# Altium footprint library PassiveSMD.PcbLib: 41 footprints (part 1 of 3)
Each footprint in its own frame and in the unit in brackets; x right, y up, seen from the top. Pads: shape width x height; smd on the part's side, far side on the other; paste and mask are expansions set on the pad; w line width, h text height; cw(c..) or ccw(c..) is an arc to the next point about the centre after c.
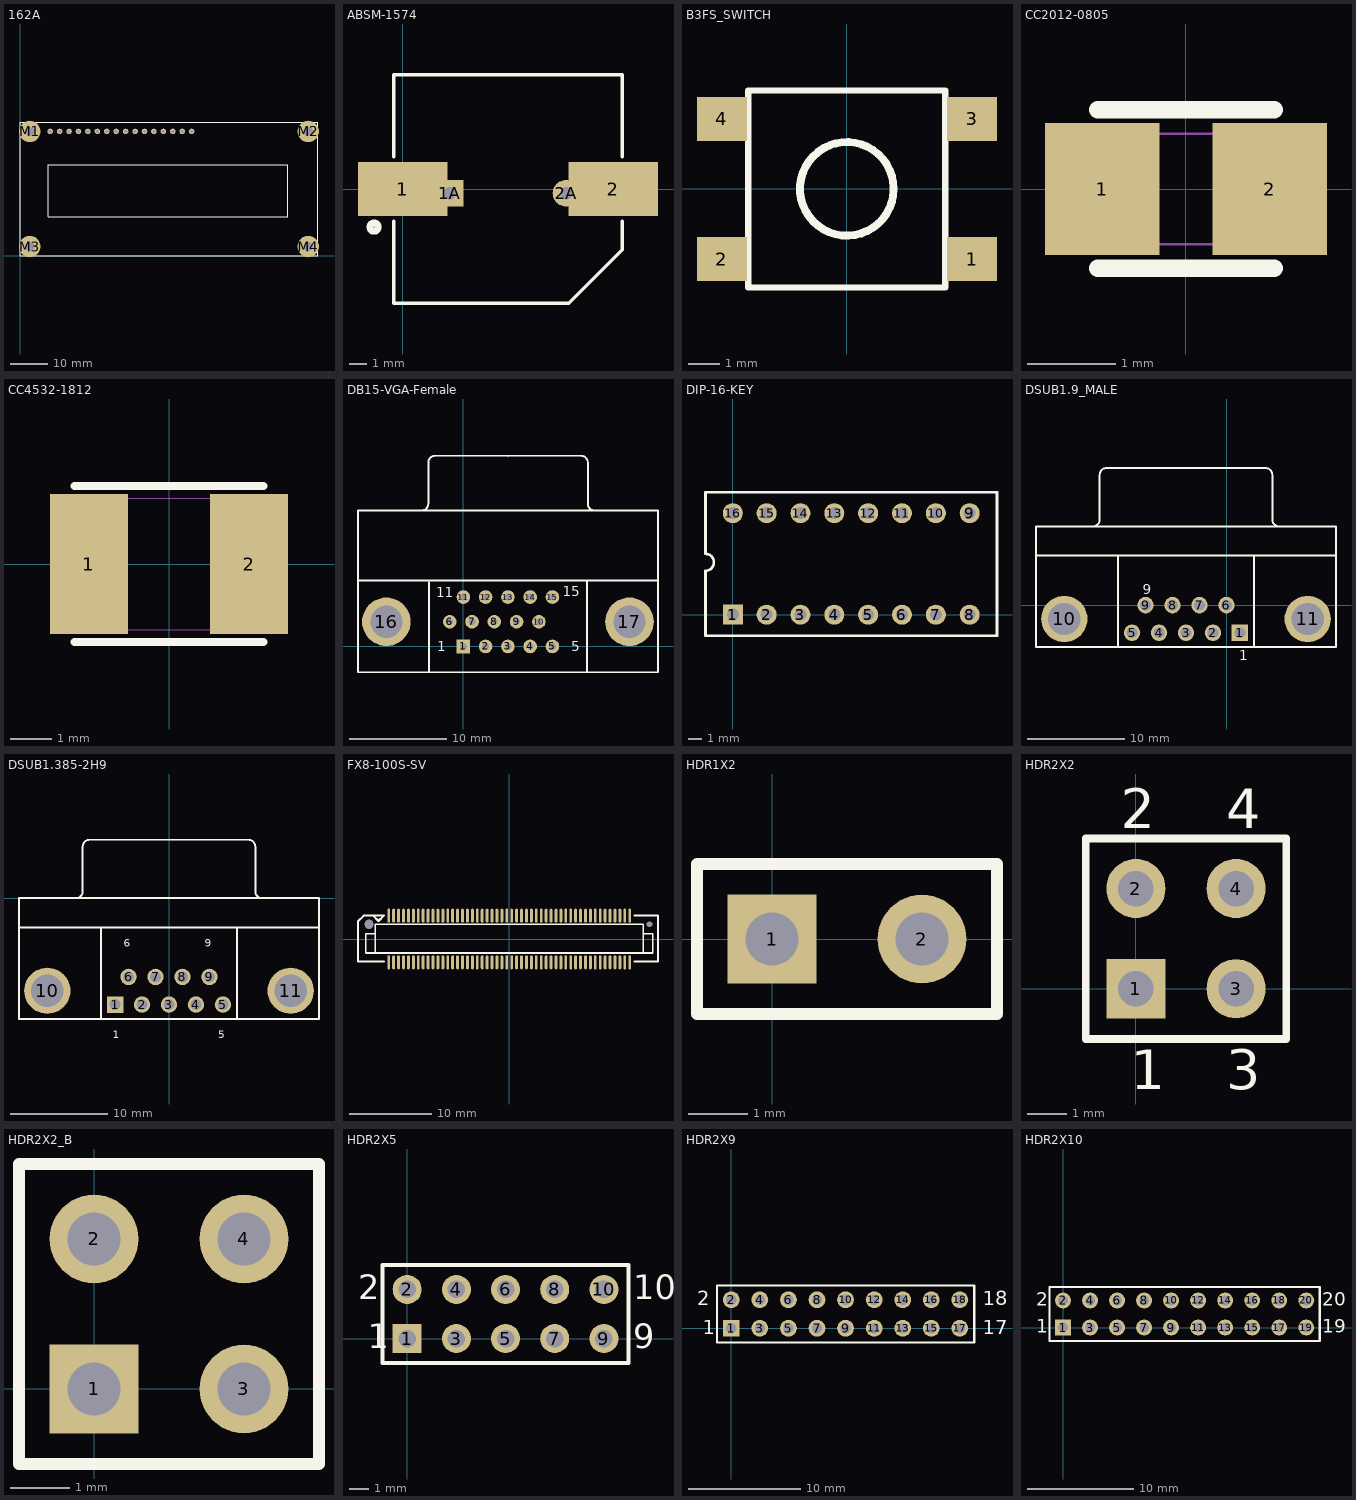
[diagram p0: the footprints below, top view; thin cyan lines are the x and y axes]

## 162A [mm]
pads (20):
  round 1.5 hole 0.9: 1(8.001,33.503) 2(10.541,33.503) 3(13.081,33.503) 4(15.621,33.503) 5(18.161,33.503) 6(20.701,33.503) 7(23.241,33.503) 8(25.781,33.503) 9(28.321,33.503) 10(30.861,33.503) 11(33.401,33.503) 12(35.941,33.503) 13(38.481,33.503) 14(41.021,33.503) 15(43.561,33.503) 16(46.101,33.503)
  round 5.8 / inner round 0 / far side round 0 hole 2.5 unplated: M1(2.501,33.503) M2(77.501,33.503) M3(2.501,2.503) M4(77.501,2.503)
Top Overlay:
  lines w0.2: 0.001,0.003 80.001,0.003 80.001,36.003 0.001,36.003 0.001,0.003 ; 7.501,10.503 72.001,10.503 72.001,24.503 7.501,24.503 7.501,10.503

## ABSM-1574 [mm]
pads (4):
  rect 5x3 smd: 1(0,0) 2(11.8,0)
  rect 1.5x1.5 hole 0.7: 1A(2.65,-0.24)
  round 1.5 hole 0.7: 2A(9.15,-0.24)
Top Overlay:
  circle w0.4: c-1.6,-2.134 r0.227
  lines w0.2: -0.5,-1.8 -0.5,-6.4 9.3,-6.4 12.3,-3.4 12.3,-1.8 ; -0.5,1.8 -0.5,6.4 12.3,6.4 12.3,1.8

## B3FS_SWITCH [mm]
pads (4):
  rect 1.6x1.4 smd: 1(4.01,-2.25) 2(-4,-2.25) 3(4.01,2.24) 4(-4,2.24)
Top Overlay:
  circle w0.254: c0,0 r1.5
  lines w0.2: -3.16,-3.16 3.15,-3.16 3.15,3.15 -3.16,3.15 -3.16,-3.16

## CC2012-0805 [mm]
pads (2):
  rect 1.3x1.5 smd: 1(-0.95,0) 2(0.95,0)
Top Overlay:
  lines w0.2: -1,-0.9 1,-0.9 ; -1,0.9 1,0.9
Mechanical 15:
  lines w0.025: -0.975,-0.625 0.975,-0.625 0.975,0.625 -0.975,0.625 -0.975,-0.625

## CC4532-1812 [mm]
pads (2):
  rect 1.9x3.4 smd: 1(-1.95,0) 2(1.95,0)
Top Overlay:
  lines w0.2: -2.3,-1.9 2.3,-1.9 ; -2.3,1.9 2.3,1.9
Mechanical 15:
  lines w0.025: -2.25,-1.6 -2.25,1.6 2.25,1.6 2.25,-1.6 -2.25,-1.6

## DB15-VGA-Female [mm]
pads (17):
  rect 1.4x1.4 hole 0.7: 1(0,0)
  round 1.4 hole 0.7: 2(2.29,0) 3(4.58,0) 4(6.87,0) 5(9.16,0) 6(-1.4,2.54) 7(0.89,2.54) 8(3.18,2.54) 9(5.47,2.54) 10(7.76,2.54) 11(0,5.08) 12(2.29,5.08) 13(4.58,5.08) 14(6.87,5.08) 15(9.16,5.08)
  round 5 hole 3.3: 16(-7.915,2.54) 17(17.075,2.54)
Top Overlay:
  lines w0.2: -10.83,6.77 20.01,6.77 ; -4.3,13.975 ccw(c-4.3,14.67) -3.605,14.67 -3.605,18.91 cw(c-2.91,18.91) -2.91,19.605 4.595,19.59 12.1,19.605 cw(c12.1,18.91) 12.795,18.91 12.795,14.67 ccw(c13.49,14.67) 13.49,13.975 ; -3.535,-2.65 -3.535,6.57 ; 12.725,-2.65 12.725,6.65 ; -10.83,-2.65 20.01,-2.65 20.01,13.97 -10.83,13.97 -10.83,-2.65
  text "1" at -2.7,-0.5 h1
  text "15" at 10.195,5.17 h1
  text "5" at 11.1,-0.5 h1
  text "11" at -2.805,5.07 h1

## DIP-16-KEY [mm]
pads (16):
  rect 1.5x1.5 hole 0.9: 1(0,0)
  round 1.5 hole 0.9: 2(2.54,0) 3(5.08,0) 4(7.62,0) 5(10.16,0) 6(12.7,0) 7(15.24,0) 8(17.78,0) 9(17.78,7.62) 10(15.24,7.62) 11(12.7,7.62) 12(10.16,7.62) 13(7.62,7.62) 14(5.08,7.62) 15(2.54,7.62) 16(0,7.62)
Top Overlay:
  lines w0.2: -2.05,4.57 cw(c-2.05,3.935) -2.05,3.3 -2.05,-1.59 19.83,-1.59 19.83,9.2 -2.05,9.2 -2.05,4.6

## DSUB1.9_MALE [mm]
pads (11):
  rect 1.69x1.69 hole 1.1: 1(1.382,-2.843)
  round 1.69 hole 1.1: 2(-1.388,-2.843) 3(-4.158,-2.843) 4(-6.928,-2.843) 5(-9.698,-2.843) 6(-0.003,-0.003) 7(-2.773,-0.003) 8(-5.543,-0.003) 9(-8.313,-0.003)
  round 4.76 hole 3.3: 10(-16.653,-1.423) 11(8.337,-1.423)
Top Overlay:
  lines w0.2: -19.558,5.077 11.242,5.077 ; -13.718,8.082 ccw(c-13.718,8.777) -13.023,8.777 -13.023,13.377 ; -13.018,13.382 cw(c-12.323,13.382) -12.323,14.077 4.007,14.077 cw(c4.007,13.382) 4.702,13.382 ; -11.158,-4.323 -11.158,5.077 ; 2.842,-4.323 2.842,5.077 ; 4.707,13.377 4.707,8.777 ccw(c5.402,8.777) 5.402,8.082 ; -19.558,-4.323 11.242,-4.323 11.242,8.077 -19.558,8.077 -19.558,-4.323
  text "9" at -8.585,1.092 h1
  text "1" at 1.321,-5.639 h1

## DSUB1.385-2H9 [mm]
pads (11):
  rect 1.69x1.69 hole 1.1: 1(-5.54,-10.92)
  round 1.69 hole 1.1: 2(-2.77,-10.92) 3(0,-10.92) 4(2.77,-10.92) 5(5.54,-10.92) 6(-4.155,-8.08) 7(-1.385,-8.08) 8(1.385,-8.08) 9(4.155,-8.08)
  round 4.76 hole 3.3: 10(-12.495,-9.5) 11(12.495,-9.5)
Top Overlay:
  lines w0.2: -15.4,-3 15.4,-3 ; -9.56,0.005 ccw(c-9.56,0.7) -8.865,0.7 -8.865,5.3 ; -8.86,5.305 cw(c-8.165,5.305) -8.165,6 8.165,6 cw(c8.165,5.305) 8.86,5.305 ; -7,-12.4 -7,-3 ; 7,-12.4 7,-3 ; 8.865,5.3 8.865,0.7 ccw(c9.56,0.7) 9.56,0.005 ; -15.4,-12.4 15.4,-12.4 15.4,0 -15.4,0 -15.4,-12.4
  text "6" at -4.655,-4.975 h0.8
  text "9" at 3.655,-4.975 h0.8
  text "5" at 5.04,-14.375 h0.8
  text "1" at -5.79,-14.375 h0.8

## FX8-100S-SV [mm]
pads (102):
  oval 0.35x1.7 smd: 1(-14.7,2.85) 2(-14.7,-2.85) 3(-14.1,2.85) 4(-14.1,-2.85) 5(-13.5,2.85) 6(-13.5,-2.85) 7(-12.9,2.85) 8(-12.9,-2.85) 9(-12.3,2.85) 10(-12.3,-2.85) 11(-11.7,2.85) 12(-11.7,-2.85) 13(-11.1,2.85) 14(-11.1,-2.85) 15(-10.5,2.85) 16(-10.5,-2.85) 17(-9.9,2.85) 18(-9.9,-2.85) 19(-9.3,2.85) 20(-9.3,-2.85) 21(-8.7,2.85) 22(-8.7,-2.85) 23(-8.1,2.85) 24(-8.1,-2.85) 25(-7.5,2.85) 26(-7.5,-2.85) 27(-6.9,2.85) 28(-6.9,-2.85) 29(-6.3,2.85) 30(-6.3,-2.85) 31(-5.7,2.85) 32(-5.7,-2.85) 33(-5.1,2.85) 34(-5.1,-2.85) 35(-4.5,2.85) 36(-4.5,-2.85) 37(-3.9,2.85) 38(-3.9,-2.85) 39(-3.3,2.85) 40(-3.3,-2.85) 41(-2.7,2.85) 42(-2.7,-2.85) 43(-2.1,2.85) 44(-2.1,-2.85) 45(-1.5,2.85) 46(-1.5,-2.85) 47(-0.9,2.85) 48(-0.9,-2.85) 49(-0.3,2.85) 50(-0.3,-2.85) 51(0.3,2.85) 52(0.3,-2.85) 53(0.9,2.85) 54(0.9,-2.85) 55(1.5,2.85) 56(1.5,-2.85) 57(2.1,2.85) 58(2.1,-2.85) 59(2.7,2.85) 60(2.7,-2.85) 61(3.3,2.85) 62(3.3,-2.85) 63(3.9,2.85) 64(3.9,-2.85) 65(4.5,2.85) 66(4.5,-2.85) 67(5.1,2.85) 68(5.1,-2.85) 69(5.7,2.85) 70(5.7,-2.85) 71(6.3,2.85) 72(6.3,-2.85) 73(6.9,2.85) 74(6.9,-2.85) 75(7.5,2.85) 76(7.5,-2.85) 77(8.1,2.85) 78(8.1,-2.85) 79(8.7,2.85) 80(8.7,-2.85) 81(9.3,2.85) 82(9.3,-2.85) 83(9.9,2.85) 84(9.9,-2.85) 85(10.5,2.85) 86(10.5,-2.85) 87(11.1,2.85) 88(11.1,-2.85) 89(11.7,2.85) 90(11.7,-2.85) 91(12.3,2.85) 92(12.3,-2.85) 93(12.9,2.85) 94(12.9,-2.85) 95(13.5,2.85) 96(13.5,-2.85) 97(14.1,2.85) 98(14.1,-2.85) 99(14.7,2.85) 100(14.7,-2.85)
  round 1 hole 1.1 unplated: M1(-17.1,1.8)
  round 0.6 hole 0.7 unplated: M2(17.1,1.8)
Top Overlay:
  lines w0.2: -16.35,0.65 -17.5,0.65 -17.5,-1.7 -16.35,-1.7 ; 16.35,0.65 17.5,0.65 17.5,-1.7 16.35,-1.7 ; -16.35,-1.7 -16.35,1.8 16.35,1.8 16.35,-1.7 ; -16.35,-1.7 16.35,-1.7
  lines w0.25: -16.6,2.85 -15.95,2.2 -15.3,2.85 -17.75,2.85 -18.45,2.15 -18.45,-2.75 -15.3,-2.75 ; 15.3,-2.75 18.15,-2.75 18.15,2.85 15.3,2.85

## HDR1X2 [mm]
pads (2):
  rect 1.5x1.5 hole 0.9: 1(0,0)
  round 1.5 hole 0.9: 2(2.54,0)
Top Overlay:
  lines w0.2: -1.27,-1.27 3.81,-1.27 3.81,1.27 -1.27,1.27 -1.27,-1.27

## HDR2X2 [mm]
pads (4):
  rect 1.5x1.5 hole 0.9: 1(0,0)
  round 1.5 hole 0.9: 2(0,2.54) 3(2.54,0) 4(2.54,2.54)
Top Overlay:
  lines w0.2: -1.27,-1.27 -1.27,3.81 3.81,3.81 3.81,-1.27 -1.27,-1.27
  text "1" at -0.127,-2.54 h1
  text "2" at -0.381,4.064 h1
  text "4" at 2.286,4.064 h1
  text "3" at 2.286,-2.54 h1

## HDR2X2_B [mm]
pads (4):
  rect 1.5x1.5 hole 0.9: 1(0,0)
  round 1.5 hole 0.9: 2(0,2.54) 3(2.54,0) 4(2.54,2.54)
Top Overlay:
  lines w0.2: -1.27,-1.27 3.81,-1.27 3.81,3.81 -1.27,3.81 -1.27,-1.27

## HDR2X5 [mm]
pads (10):
  rect 1.5x1.5 hole 0.9: 1(0,0)
  round 1.5 hole 0.9: 2(0,2.54) 3(2.54,0) 4(2.54,2.54) 5(5.08,0) 6(5.08,2.54) 7(7.62,0) 8(7.62,2.54) 9(10.16,0) 10(10.16,2.54)
Top Overlay:
  lines w0.2: -1.27,-1.27 11.43,-1.27 11.43,3.81 -1.27,3.81 -1.27,-1.27
  text "10" at 11.684,2.032 h1.27
  text "9" at 11.684,-0.508 h1.27
  text "1" at -2.032,-0.508 h1.27
  text "2" at -2.54,2.032 h1.27

## HDR2X9 [mm]
pads (18):
  rect 1.5x1.5 hole 0.9: 1(0,0)
  round 1.5 hole 0.9: 2(0,2.54) 3(2.54,0) 4(2.54,2.54) 5(5.08,0) 6(5.08,2.54) 7(7.62,0) 8(7.62,2.54) 9(10.16,0) 10(10.16,2.54) 11(12.7,0) 12(12.7,2.54) 13(15.24,0) 14(15.24,2.54) 15(17.78,0) 16(17.78,2.54) 17(20.32,0) 18(20.32,2.54)
Top Overlay:
  lines w0.2: -1.27,-1.27 21.59,-1.27 21.59,3.81 -1.27,3.81 -1.27,-1.27
  text "18" at 22.352,2.032 h1.27
  text "17" at 22.352,-0.508 h1.27
  text "1" at -2.54,-0.508 h1.27
  text "2" at -3.048,2.032 h1.27

## HDR2X10 [mm]
pads (20):
  rect 1.5x1.5 hole 0.9: 1(0,0)
  round 1.5 hole 0.9: 2(0,2.54) 3(2.54,0) 4(2.54,2.54) 5(5.08,0) 6(5.08,2.54) 7(7.62,0) 8(7.62,2.54) 9(10.16,0) 10(10.16,2.54) 11(12.7,0) 12(12.7,2.54) 13(15.24,0) 14(15.24,2.54) 15(17.78,0) 16(17.78,2.54) 17(20.32,0) 18(20.32,2.54) 19(22.86,0) 20(22.86,2.54)
Top Overlay:
  lines w0.2: -1.27,-1.27 -1.27,3.81 24.13,3.81 24.13,-1.27 -1.27,-1.27
  text "20" at 24.384,2.032 h1.27
  text "19" at 24.384,-0.508 h1.27
  text "1" at -2.54,-0.508 h1.27
  text "2" at -2.54,2.032 h1.27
